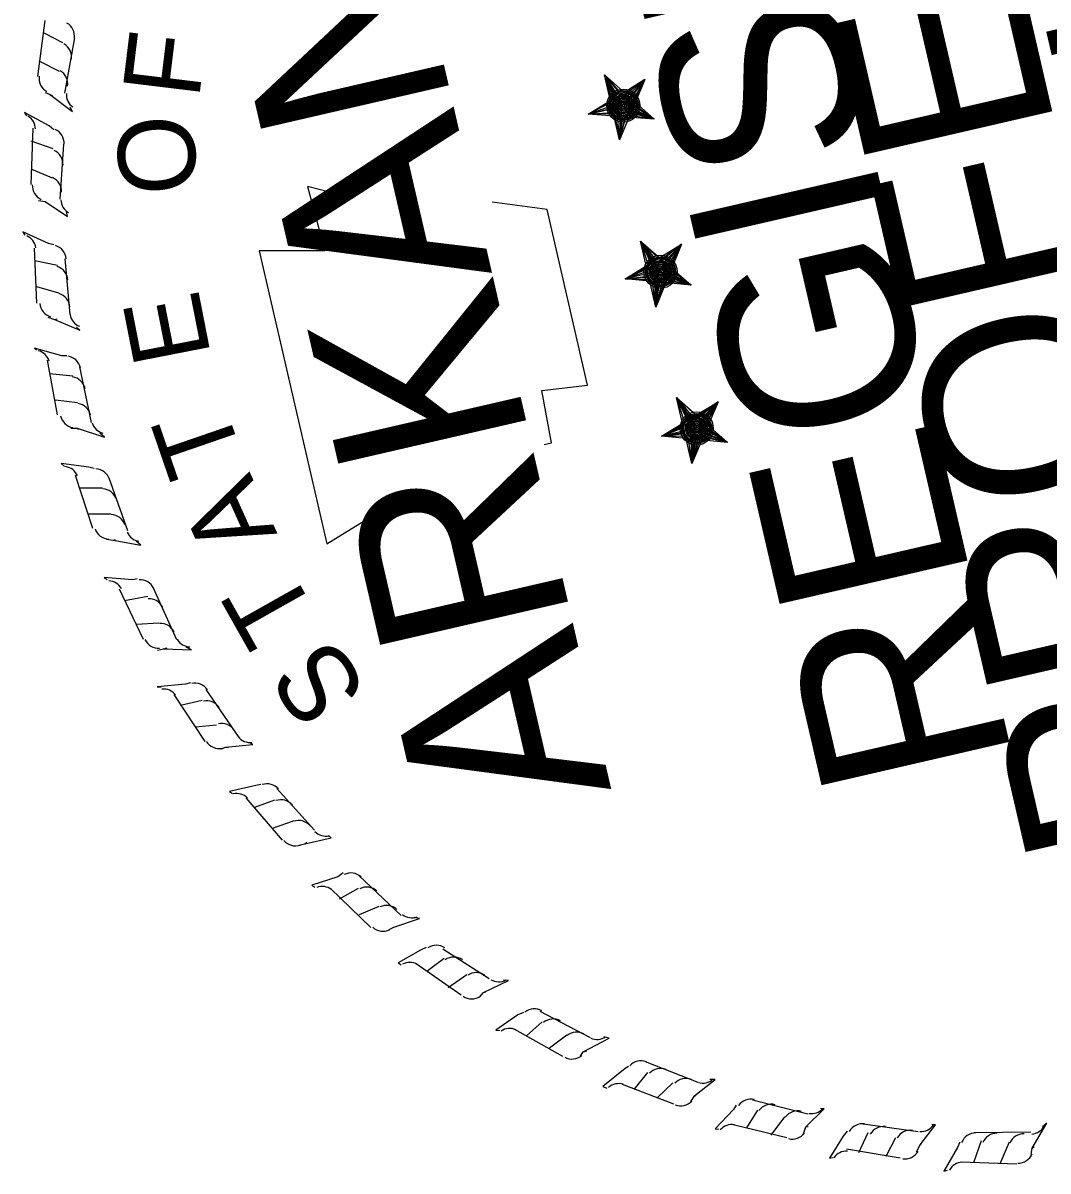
# Model space of a CAD drawing. Extents: x 634644 to 1109343, y 286699 to 700411.
# Drawn here: x 1108871.4 to 1108921.3, y 700185.7 to 700241.6 of the extents above; entities that cross this region are included whole.
import ezdxf

# ---------------------------------------------------------------- set-up
doc = ezdxf.new("R2010")
doc.units = 0
doc.layers.add('S_PRIMARY_CTL', color=7, linetype='Continuous')

msp = doc.modelspace()

# ---------------------------------------------------------------- linework, layer by layer
at = {"layer": 'S_PRIMARY_CTL'}
for p, q in [((1108872.163, 700238.972), (1108872.518, 700241.702)), ((1108873.386, 700240.609), (1108872.478, 700241.076)), ((1108873.944, 700240.861), (1108873.459, 700238.162)), ((1108873.216, 700239.215), (1108872.235, 700239.727)), ((1108899.731, 700239.055), (1108900.577, 700237.526)), ((1108899.731, 700239.055), (1108900.113, 700237.666)), ((1108899.731, 700239.055), (1108900.217, 700237.751)), ((1108899.731, 700239.055), (1108900.334, 700237.778)), ((1108899.731, 700239.055), (1108900.325, 700238.084)), ((1108899.731, 700239.055), (1108900.415, 700238.228)), ((1108899.731, 700239.055), (1108900.401, 700238.286)), ((1108901.692, 700238.831), (1108900.455, 700238.052)), ((1108901.692, 700238.831), (1108900.541, 700237.949)), ((1108901.692, 700238.831), (1108900.577, 700237.526)), ((1108901.692, 700238.831), (1108900.729, 700237.931)), ((1108901.692, 700238.831), (1108900.932, 700237.855)), ((1108901.692, 700238.831), (1108900.986, 700237.621)), ((1108901.692, 700238.831), (1108901.103, 700237.648)), ((1108872.528, 700238.194), (1108872.73, 700238.117)), ((1108872.73, 700238.117), (1108873.85, 700237.267)), ((1108872.73, 700238.117), (1108872.874, 700238.027)), ((1108873.85, 700237.267), (1108873.737, 700237.488)), ((1108898.94, 700237.148), (1108899.969, 700237.756)), ((1108898.94, 700237.148), (1108899.983, 700237.697)), ((1108900.577, 700237.526), (1108898.94, 700237.148)), ((1108898.94, 700237.148), (1108900.023, 700237.522)), ((1108898.94, 700237.148), (1108900.05, 700237.405)), ((1108900.46, 700235.898), (1108900.577, 700237.526)), ((1108902.137, 700236.901), (1108900.577, 700237.526)), ((1108902.137, 700236.901), (1108900.986, 700237.621)), ((1108902.137, 700236.901), (1108901.026, 700237.445)), ((1108902.137, 700236.901), (1108901.031, 700237.693)), ((1108872.717, 700236.575), (1108871.52, 700237.222)), ((1108871.52, 700237.222), (1108871.619, 700237.06)), ((1108898.94, 700237.148), (1108900.091, 700237.229)), ((1108898.94, 700237.148), (1108900.104, 700237.171)), ((1108900.46, 700235.898), (1108900.248, 700237.081)), ((1108900.46, 700235.898), (1108900.365, 700237.108)), ((1108900.46, 700235.898), (1108900.802, 700237.086)), ((1108900.46, 700235.898), (1108900.743, 700237.072)), ((1108900.46, 700235.898), (1108900.626, 700237.045)), ((1108900.46, 700235.898), (1108900.509, 700237.018)), ((1108902.137, 700236.901), (1108900.802, 700237.086)), ((1108902.137, 700236.901), (1108900.891, 700237.229)), ((1108902.137, 700236.901), (1108900.936, 700237.301)), ((1108871.836, 700233.723), (1108871.943, 700236.458)), ((1108872.946, 700236.381), (1108872.717, 700236.575)), ((1108872.915, 700235.45), (1108871.844, 700235.819)), ((1108873.414, 700235.689), (1108873.234, 700233)), ((1108872.874, 700234.025), (1108871.849, 700234.465)), ((1108872.2, 700232.945), (1108872.519, 700232.896)), ((1108872.519, 700232.896), (1108873.612, 700232.163)), ((1108872.519, 700232.896), (1108872.533, 700232.838)), ((1108873.612, 700232.163), (1108873.558, 700232.397)), ((1108872.686, 700230.841), (1108871.444, 700231.416)), ((1108871.444, 700231.416), (1108871.543, 700231.254)), ((1108872.947, 700230.778), (1108872.686, 700230.841)), ((1108901.477, 700230.96), (1108902.367, 700229.503)), ((1108901.477, 700230.96), (1108901.918, 700229.584)), ((1108901.477, 700230.96), (1108902.079, 700229.683)), ((1108901.477, 700230.96), (1108902.138, 700229.697)), ((1108901.477, 700230.96), (1108902.129, 700230.003)), ((1108901.477, 700230.96), (1108902.16, 700230.133)), ((1108901.477, 700230.96), (1108902.264, 700230.219)), ((1108903.482, 700230.808), (1108902.331, 700229.926)), ((1108903.482, 700230.808), (1108902.345, 700229.868)), ((1108903.482, 700230.808), (1108902.367, 700229.503)), ((1108903.482, 700230.808), (1108902.534, 700229.85)), ((1108903.482, 700230.808), (1108902.75, 700229.715)), ((1108903.482, 700230.808), (1108902.79, 700229.539)), ((1108903.482, 700230.808), (1108902.848, 700229.553)), ((1108872.124, 700227.94), (1108871.998, 700230.62)), ((1108873.473, 700230.099), (1108873.729, 700227.387)), ((1108873.118, 700229.771), (1108872.016, 700230.009)), ((1108900.73, 700229.126), (1108901.774, 700229.674)), ((1108900.73, 700229.126), (1108901.787, 700229.616)), ((1108903.941, 700228.82), (1108902.732, 700229.526)), ((1108903.941, 700228.82), (1108902.835, 700229.611)), ((1108902.367, 700229.503), (1108900.73, 700229.126)), ((1108900.73, 700229.126), (1108901.814, 700229.499)), ((1108900.73, 700229.126), (1108901.868, 700229.265)), ((1108900.73, 700229.126), (1108901.882, 700229.207)), ((1108900.73, 700229.126), (1108901.909, 700229.09)), ((1108902.219, 700227.745), (1108902.183, 700228.968)), ((1108902.219, 700227.745), (1108902.367, 700229.503)), ((1108902.219, 700227.745), (1108902.417, 700229.022)), ((1108902.219, 700227.745), (1108902.664, 700229.018)), ((1108902.219, 700227.745), (1108902.547, 700228.991)), ((1108902.219, 700227.745), (1108902.241, 700228.982)), ((1108903.941, 700228.82), (1108902.367, 700229.503)), ((1108903.941, 700228.82), (1108902.592, 700229.063)), ((1108903.941, 700228.82), (1108902.709, 700229.09)), ((1108903.941, 700228.82), (1108902.741, 700229.22)), ((1108903.941, 700228.82), (1108902.817, 700229.423)), ((1108873.181, 700228.43), (1108872.124, 700228.741)), ((1108902.219, 700227.745), (1108902.066, 700228.941)), ((1108872.65, 700227.261), (1108872.983, 700227.153)), ((1108872.983, 700227.153), (1108873.1, 700227.18)), ((1108872.983, 700227.153), (1108874.211, 700226.636)), ((1108874.211, 700226.636), (1108874.053, 700226.785)), ((1108873.329, 700225.386), (1108872.012, 700225.759)), ((1108872.012, 700225.759), (1108872.097, 700225.656)), ((1108873.132, 700222.508), (1108872.641, 700225.165)), ((1108873.577, 700225.381), (1108873.329, 700225.386)), ((1108873.865, 700224.401), (1108872.731, 700224.509)), ((1108874.193, 700224.846), (1108874.755, 700222.143)), ((1108874.103, 700223.101), (1108873.028, 700223.223)), ((1108903.231, 700223.36), (1108904.135, 700221.845)), ((1108903.231, 700223.36), (1108903.686, 700221.926)), ((1108903.231, 700223.36), (1108903.834, 700222.083)), ((1108903.231, 700223.36), (1108903.893, 700222.097)), ((1108903.231, 700223.36), (1108903.883, 700222.403)), ((1108903.231, 700223.36), (1108903.915, 700222.533)), ((1108903.231, 700223.36), (1108904.018, 700222.618)), ((1108905.251, 700223.149), (1108904.086, 700222.326)), ((1108905.251, 700223.149), (1108904.113, 700222.209)), ((1108905.251, 700223.149), (1108904.135, 700221.845)), ((1108905.251, 700223.149), (1108904.302, 700222.191)), ((1108905.251, 700223.149), (1108904.504, 700222.115)), ((1108905.251, 700223.149), (1108904.545, 700221.939)), ((1108905.251, 700223.149), (1108904.603, 700221.953)), ((1108873.775, 700221.856), (1108874.081, 700221.865)), ((1108874.081, 700221.865), (1108875.412, 700221.433)), ((1108874.081, 700221.865), (1108874.153, 700221.82)), ((1108902.498, 700221.467), (1108903.542, 700222.016)), ((1108902.498, 700221.467), (1108903.555, 700221.957)), ((1108902.498, 700221.467), (1108903.569, 700221.899)), ((1108904.135, 700221.845), (1108902.498, 700221.467)), ((1108903.974, 700220.145), (1108904.135, 700221.845)), ((1108905.709, 700221.162), (1108904.135, 700221.845)), ((1108905.709, 700221.162), (1108904.486, 700221.926)), ((1108905.709, 700221.162), (1108904.572, 700221.822)), ((1108905.709, 700221.162), (1108904.603, 700221.953)), ((1108875.412, 700221.433), (1108875.183, 700221.626)), ((1108902.498, 700221.467), (1108903.623, 700221.665)), ((1108902.498, 700221.467), (1108903.636, 700221.607)), ((1108902.498, 700221.467), (1108903.663, 700221.49)), ((1108903.974, 700220.145), (1108903.821, 700221.341)), ((1108903.974, 700220.145), (1108903.938, 700221.368)), ((1108903.974, 700220.145), (1108904.419, 700221.418)), ((1108903.974, 700220.145), (1108904.302, 700221.391)), ((1108903.974, 700220.145), (1108903.996, 700221.382)), ((1108903.974, 700220.145), (1108904.185, 700221.364)), ((1108905.709, 700221.162), (1108904.347, 700221.463)), ((1108905.709, 700221.162), (1108904.464, 700221.49)), ((1108905.709, 700221.162), (1108904.495, 700221.62)), ((1108874.643, 700219.962), (1108873.307, 700220.147)), ((1108873.307, 700220.147), (1108873.465, 700219.998)), ((1108874.837, 700216.99), (1108873.995, 700219.567)), ((1108874.904, 700219.899), (1108874.643, 700219.962)), ((1108875.309, 700218.946), (1108874.202, 700218.937)), ((1108875.623, 700219.45), (1108876.523, 700216.886)), ((1108875.723, 700217.687), (1108874.616, 700217.678)), ((1108875.511, 700216.468), (1108875.831, 700216.419)), ((1108875.831, 700216.419), (1108875.948, 700216.446)), ((1108875.831, 700216.419), (1108877.18, 700216.176)), ((1108877.18, 700216.176), (1108876.95, 700216.369)), ((1108876.771, 700214.48), (1108875.39, 700214.593)), ((1108875.39, 700214.593), (1108875.534, 700214.503)), ((1108877.005, 700214.534), (1108876.771, 700214.48)), ((1108877.315, 700211.589), (1108876.137, 700214.026)), ((1108877.783, 700214.098), (1108878.916, 700211.589)), ((1108877.513, 700213.667), (1108876.389, 700213.469)), ((1108878.057, 700212.376), (1108876.964, 700212.308)), ((1108877.99, 700211.067), (1108878.282, 700211.135)), ((1108878.282, 700211.135), (1108878.457, 700211.175)), ((1108878.282, 700211.135), (1108879.649, 700211.081)), ((1108879.649, 700211.081), (1108879.375, 700211.202)), ((1108879.591, 700209.466), (1108879.357, 700209.412)), ((1108879.357, 700209.412), (1108877.972, 700209.277)), ((1108877.972, 700209.277), (1108878.161, 700209.259)), ((1108880.311, 700206.615), (1108878.795, 700208.913)), ((1108880.342, 700209.147), (1108881.916, 700206.863)), ((1108880.158, 700208.612), (1108879.105, 700208.369)), ((1108880.864, 700207.42), (1108879.843, 700207.308)), ((1108881.075, 700206.238), (1108881.296, 700206.35)), ((1108881.296, 700206.35), (1108882.622, 700206.472)), ((1108881.296, 700206.35), (1108881.426, 700206.319)), ((1108882.622, 700206.472), (1108882.478, 700206.561)), ((1108882.775, 700204.475), (1108881.489, 700204.178)), ((1108883.009, 700204.529), (1108882.775, 700204.475)), ((1108881.489, 700204.178), (1108881.633, 700204.088)), ((1108884.066, 700201.817), (1108882.299, 700203.872)), ((1108883.792, 700204.34), (1108885.618, 700202.298)), ((1108883.679, 700203.76), (1108882.713, 700203.413)), ((1108884.592, 700202.739), (1108883.567, 700202.379)), ((1108884.862, 700201.57), (1108885.155, 700201.637)), ((1108885.155, 700201.637), (1108886.441, 700201.934)), ((1108885.155, 700201.637), (1108885.258, 700201.723)), ((1108886.441, 700201.934), (1108886.297, 700202.024)), ((1108886.756, 700200.036), (1108885.497, 700199.623)), ((1108887.021, 700200.221), (1108886.756, 700200.036)), ((1108887.79, 700200.091), (1108889.837, 700198.161)), ((1108885.497, 700199.623), (1108885.641, 700199.533)), ((1108888.371, 700197.577), (1108886.396, 700199.461)), ((1108887.75, 700199.465), (1108886.823, 700198.944)), ((1108888.753, 700198.589), (1108887.799, 700198.184)), ((1108889.477, 700197.586), (1108890.736, 700198)), ((1108890.736, 700198), (1108890.475, 700198.063)), ((1108889.256, 700197.473), (1108889.477, 700197.586)), ((1108889.477, 700197.586), (1108889.594, 700197.613)), ((1108891.06, 700196.597), (1108890.781, 700196.471)), ((1108890.781, 700196.471), (1108889.693, 700195.85)), ((1108891.923, 700196.057), (1108891.083, 700195.432)), ((1108891.874, 700196.538), (1108894.118, 700195.086)), ((1108889.693, 700195.85), (1108889.837, 700195.76)), ((1108892.765, 700194.281), (1108890.565, 700195.805)), ((1108893.03, 700195.266), (1108892.13, 700194.627)), ((1108893.844, 700194.407), (1108895.063, 700194.996)), ((1108895.063, 700194.996), (1108894.815, 700195)), ((1108893.651, 700194.177), (1108893.844, 700194.407)), ((1108893.844, 700194.407), (1108893.961, 700194.434)), ((1108895.512, 700193.314), (1108894.451, 700192.576)), ((1108895.791, 700193.44), (1108895.512, 700193.314)), ((1108896.578, 700193.498), (1108899.029, 700192.217)), ((1108896.7, 700192.972), (1108895.931, 700192.302)), ((1108894.451, 700192.576), (1108894.64, 700192.558)), ((1108897.703, 700191.295), (1108895.369, 700192.603)), ((1108897.896, 700192.325), (1108897.055, 700191.7)), ((1108898.697, 700191.524), (1108899.96, 700192.186)), ((1108899.96, 700192.186), (1108899.699, 700192.249)), ((1108898.697, 700191.524), (1108898.872, 700191.565)), ((1108898.562, 700191.309), (1108898.697, 700191.524)), ((1108901.701, 700191.048), (1108904.273, 700190.041)), ((1108900.734, 700190.702), (1108899.641, 700189.834)), ((1108900.896, 700190.801), (1108900.734, 700190.702)), ((1108901.822, 700190.522), (1108901.152, 700189.69)), ((1108903.104, 700188.97), (1108900.604, 700189.933)), ((1108903.05, 700190.005), (1108902.295, 700189.276)), ((1108904.116, 700189.389), (1108905.105, 700190.171)), ((1108905.105, 700190.171), (1108904.858, 700190.176)), ((1108899.641, 700189.834), (1108899.844, 700189.757)), ((1108903.936, 700189.101), (1108904.116, 700189.389)), ((1108904.116, 700189.389), (1108904.174, 700189.402)), ((1108906.131, 700188.93), (1108905.996, 700188.714)), ((1108906.936, 700189.178), (1108909.616, 700188.503)), ((1108909.517, 700187.865), (1108910.421, 700188.751)), ((1108910.421, 700188.751), (1108910.232, 700188.769)), ((1108905.996, 700188.714), (1108905.105, 700187.77)), ((1108907.174, 700188.679), (1108906.635, 700187.815)), ((1108908.478, 700188.364), (1108907.822, 700187.473)), ((1108905.105, 700187.77), (1108905.294, 700187.752)), ((1108908.591, 700187.343), (1108905.982, 700187.972)), ((1108909.409, 700187.532), (1108909.517, 700187.865)), ((1108909.517, 700187.865), (1108909.634, 700187.892)), ((1108911.536, 700187.654), (1108911.343, 700187.424)), ((1108912.314, 700188.018), (1108914.986, 700187.649)), ((1108915.076, 700186.993), (1108915.836, 700187.969)), ((1108915.836, 700187.969), (1108915.647, 700187.987)), ((1108920.531, 700186.836), (1108921.237, 700188.046)), ((1108921.237, 700188.046), (1108921.03, 700187.875)), ((1108911.343, 700187.424), (1108910.669, 700186.345)), ((1108912.539, 700187.577), (1108912.085, 700186.61)), ((1108913.889, 700187.334), (1108913.421, 700186.426)), ((1108917.014, 700187.132), (1108916.893, 700186.858)), ((1108918.048, 700187.186), (1108917.68, 700186.116)), ((1108917.707, 700187.6), (1108920.472, 700187.623)), ((1108919.416, 700187.133), (1108918.975, 700186.107)), ((1108914.118, 700186.341), (1108911.492, 700186.781)), ((1108914.909, 700186.647), (1108915.076, 700186.993)), ((1108915.076, 700186.993), (1108915.134, 700187.006)), ((1108916.893, 700186.858), (1108916.232, 700185.72)), ((1108920.481, 700186.517), (1108920.531, 700186.836)), ((1108920.531, 700186.836), (1108920.634, 700186.921)), ((1108910.669, 700186.345), (1108910.844, 700186.385)), ((1108919.789, 700186.049), (1108917.055, 700186.157)), ((1108916.232, 700185.72), (1108916.407, 700185.761))]:
    msp.add_line(p, q, dxfattribs=at)
for points in [[(1108898.94, 700237.148), (1108901.692, 700238.831), (1108900.46, 700235.898), (1108899.731, 700239.055), (1108902.137, 700236.901), (1108898.94, 700237.148)], [(1108886.789, 700233.235), (1108885.282, 700233.626), (1108886.128, 700230.496), (1108882.926, 700230.496), (1108886.219, 700216.231)], [(1108896.801, 700221.075), (1108897.151, 700221.156), (1108896.688, 700223.697), (1108898.905, 700223.963), (1108896.934, 700232.498), (1108894.263, 700232.867)], [(1108900.73, 700229.126), (1108903.482, 700230.808), (1108902.219, 700227.745), (1108901.477, 700230.96), (1108903.941, 700228.82), (1108900.73, 700229.126)], [(1108902.498, 700221.467), (1108905.251, 700223.149), (1108903.974, 700220.145), (1108903.231, 700223.36), (1108905.709, 700221.162), (1108902.498, 700221.467)], [(1108886.219, 700216.231), (1108889.722, 700218.394)]]:
    msp.add_lwpolyline(points, dxfattribs=at)
for centre, radius in [((1108900.646, 700237.558), 0.807), ((1108900.646, 700237.558), 0.731), ((1108900.646, 700237.558), 0.678), ((1108900.646, 700237.558), 0.622), ((1108900.646, 700237.558), 0.543), ((1108900.646, 700237.558), 0.504), ((1108900.646, 700237.558), 0.464), ((1108900.646, 700237.558), 0.4), ((1108900.646, 700237.558), 0.35), ((1108900.646, 700237.558), 0.291), ((1108900.646, 700237.558), 0.232), ((1108900.646, 700237.558), 0.173), ((1108900.646, 700237.558), 0.139), ((1108900.646, 700237.558), 0.0676), ((1108902.455, 700229.474), 0.807), ((1108902.455, 700229.474), 0.731), ((1108902.455, 700229.474), 0.678), ((1108902.455, 700229.474), 0.622), ((1108902.455, 700229.474), 0.543), ((1108902.455, 700229.474), 0.504), ((1108902.455, 700229.474), 0.464), ((1108902.455, 700229.474), 0.4), ((1108902.455, 700229.474), 0.35), ((1108902.455, 700229.474), 0.291), ((1108902.455, 700229.474), 0.232), ((1108902.455, 700229.474), 0.173), ((1108902.455, 700229.474), 0.139), ((1108902.455, 700229.474), 0.0676), ((1108904.215, 700221.851), 0.807), ((1108904.215, 700221.851), 0.731), ((1108904.215, 700221.851), 0.678), ((1108904.215, 700221.851), 0.622), ((1108904.215, 700221.851), 0.543), ((1108904.215, 700221.851), 0.504), ((1108904.215, 700221.851), 0.464), ((1108904.215, 700221.851), 0.4), ((1108904.215, 700221.851), 0.35), ((1108904.215, 700221.851), 0.291), ((1108904.215, 700221.851), 0.232), ((1108904.215, 700221.851), 0.173), ((1108904.215, 700221.851), 0.139), ((1108904.215, 700221.851), 0.0676)]:
    msp.add_circle(centre, radius, dxfattribs=at)
for centre, start, end in [((1108873.21, 700240.932), 352.0955, 60.4695), ((1108873.072, 700239.915), 352.0955, 60.4695), ((1108872.885, 700238.606), 352.0955, 60.4695), ((1108872.966, 700238.883), 172.0955, 240.4695), ((1108874.295, 700238.093), 176.3563, 235.1441), ((1108871.314, 700236.403), 1.2517, 60.0395), ((1108872.705, 700235.729), 356.9909, 65.3649), ((1108872.654, 700234.704), 356.9909, 65.3649), ((1108872.579, 700233.384), 356.9909, 65.3649), ((1108872.637, 700233.667), 176.9909, 245.3649), ((1108874.028, 700232.993), 181.2517, 240.0395), ((1108871.342, 700230.532), 8.6839, 67.4717), ((1108872.808, 700230.044), 4.4231, 72.797), ((1108872.89, 700229.021), 4.4231, 72.797), ((1108872.987, 700227.703), 4.4231, 72.797), ((1108873.008, 700227.99), 184.4231, 252.797), ((1108874.474, 700227.502), 188.6839, 247.4717), ((1108872.002, 700224.918), 16.4236, 75.2115), ((1108873.52, 700224.632), 12.1628, 80.5368), ((1108873.74, 700223.629), 12.1628, 80.5368), ((1108874.013, 700222.335), 12.1628, 80.5368), ((1108873.995, 700222.623), 192.1628, 260.5368), ((1108875.514, 700222.337), 196.4236, 255.2115), ((1108873.413, 700219.259), 22.9249, 81.7128), ((1108874.954, 700219.146), 18.6641, 87.0381), ((1108875.286, 700218.174), 18.6641, 87.0381), ((1108875.704, 700216.92), 18.6641, 87.0381), ((1108875.653, 700217.204), 198.6641, 267.0381), ((1108877.194, 700217.092), 202.9249, 261.7128), ((1108877.137, 700213.752), 25.0093, 93.3832), ((1108875.593, 700213.693), 29.2701, 88.0579), ((1108877.574, 700212.823), 25.0093, 93.3832), ((1108878.128, 700211.623), 25.0093, 93.3832), ((1108878.047, 700211.899), 205.0093, 273.3832), ((1108879.591, 700211.958), 209.2701, 268.0579), ((1108879.803, 700208.717), 33.5763, 101.9503), ((1108878.285, 700208.429), 37.8371, 96.6249), ((1108880.374, 700207.864), 33.5763, 101.9503), ((1108881.101, 700206.759), 33.5763, 101.9503), ((1108882.497, 700207.309), 217.8371, 276.6249), ((1108880.978, 700207.021), 213.5763, 281.9503), ((1108883.32, 700203.82), 40.6937, 109.0677), ((1108881.849, 700203.346), 44.9545, 103.7423), ((1108883.991, 700203.043), 40.6937, 109.0677), ((1108884.849, 700202.038), 40.6937, 109.0677), ((1108886.167, 700202.756), 224.9545, 283.7423), ((1108884.696, 700202.282), 220.6937, 289.0677), ((1108887.396, 700199.481), 47.8528, 116.2267), ((1108885.996, 700198.827), 52.1135, 110.9014), ((1108888.159, 700198.794), 47.8528, 116.2267), ((1108889.136, 700197.903), 47.8528, 116.2267), ((1108890.353, 700198.78), 232.1135, 290.9014), ((1108888.953, 700198.127), 227.8528, 296.2267), ((1108891.552, 700195.965), 55.5627, 123.9367), ((1108892.4, 700195.387), 55.5627, 123.9367), ((1108890.252, 700195.13), 59.8235, 118.6113), ((1108893.488, 700194.635), 55.5627, 123.9367), ((1108894.577, 700195.667), 239.8235, 298.6113), ((1108893.276, 700194.832), 235.5627, 303.9367), ((1108896.329, 700192.875), 61.0045, 129.3785), ((1108895.114, 700191.92), 65.2653, 124.0531), ((1108897.228, 700192.38), 61.0045, 129.3785), ((1108898.382, 700191.735), 61.0045, 129.3785), ((1108899.368, 700192.865), 245.2653, 304.0531), ((1108898.153, 700191.91), 241.0045, 309.3785), ((1108901.497, 700190.342), 68.7028, 137.0768), ((1108902.455, 700189.973), 68.7028, 137.0768), ((1108900.421, 700189.233), 72.9636, 131.7515), ((1108903.685, 700189.488), 68.7028, 137.0768), ((1108904.511, 700190.74), 252.9636, 311.7515), ((1108903.434, 700189.631), 248.7028, 317.0768), ((1108906.847, 700188.476), 75.9635, 144.3375), ((1108907.844, 700188.23), 75.9635, 144.3375), ((1108909.786, 700189.251), 260.2243, 319.0121), ((1108909.125, 700187.905), 75.9635, 144.3375), ((1108905.92, 700187.24), 80.2243, 139.0121), ((1108912.283, 700187.281), 82.3857, 150.7597), ((1108913.301, 700187.148), 82.3857, 150.7597), ((1108914.611, 700186.967), 82.3857, 150.7597), ((1108915.117, 700188.38), 266.6465, 325.4343), ((1108920.467, 700188.258), 273.445, 332.2329), ((1108908.859, 700188.015), 255.9635, 324.3375), ((1108917.784, 700186.831), 89.1842, 157.5582), ((1108918.81, 700186.82), 89.1842, 157.5582), ((1108920.132, 700186.796), 89.1842, 157.5582), ((1108911.5, 700185.948), 86.6465, 145.4343), ((1108914.334, 700187.048), 262.3857, 330.7597), ((1108919.847, 700186.843), 269.1842, 337.5582), ((1108917.164, 700185.416), 93.445, 152.2329)]:
    msp.add_arc(centre, 0.74, start, end, dxfattribs=at)

# ---------------------------------------------------------------- texts
for s, height, rotation, p in [('PROFESSIONAL', 9.37438, 103, (1108929.573, 700202.348)), ('REGISTERED', 9.3744, 103, (1108919.648, 700205.598)), ('ENGINEER', 9.3744, 103, (1108936.983, 700214.527)), ('ARKANSAS', 9.3744, 103, (1108900.063, 700204.279)), ('F', 3.748, 83.0707, (1108880.002, 700237.826)), ('O', 3.748, 93.4515, (1108879.935, 700233.315)), ('E', 3.75, 101.0732, (1108880.592, 700225.4)), ('T', 3.75, 109.0228, (1108882.189, 700220.35)), ('A', 3.749, 114.2132, (1108883.827, 700216.725)), ('T', 3.75, 119.4036, (1108885.806, 700212.687)), ('S', 3.75, 124.594, (1108888.302, 700209.076))]:
    msp.add_text(s, height=height, rotation=rotation, dxfattribs=at).set_placement(p)

doc.saveas('drawing.dxf')
